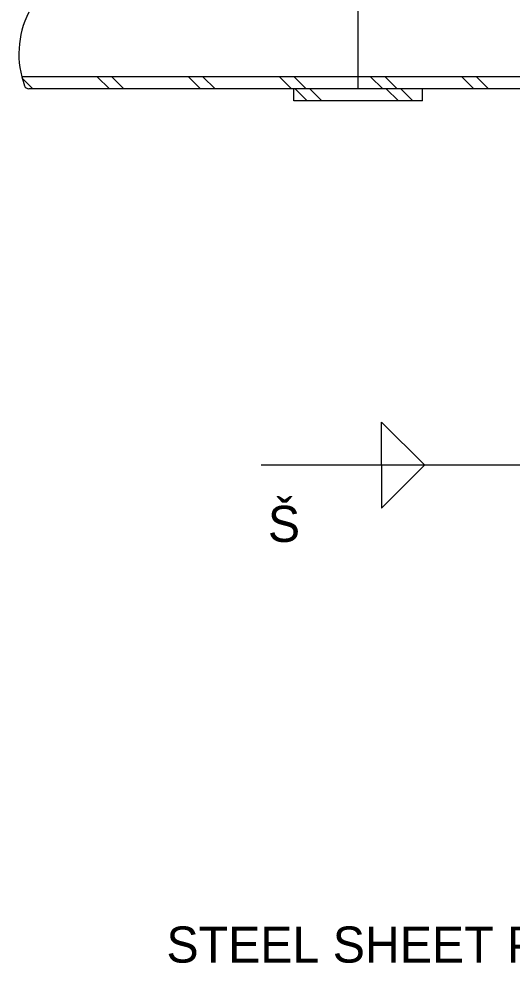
# Model space of a CAD drawing. Extents: x 22411.4 to 22495.4, y 22369.6 to 22415.
# Drawn here: x 22412.036 to 22414.588, y 22387.925 to 22392.809 of the extents above; entities that cross this region are included whole.
import ezdxf

# ---------------------------------------------------------------- set-up
doc = ezdxf.new("R2010")
doc.units = 0
for name, color, linetype in [('Level 1', 7, 'Continuous'), ('Level 10', 7, 'Continuous'), ('Level 2', 7, 'Continuous'), ('Level 4', 7, 'Continuous'), ('Level 8', 7, 'Continuous')]:
    doc.layers.add(name, color=color, linetype=linetype)

msp = doc.modelspace()

# ---------------------------------------------------------------- linework, layer by layer
at = {"layer": 'Level 1'}
for centre, radius, start, end in [((22412.516, 22392.6285), 0.4798, 153.3929, 200.1919), ((22412.0877, 22392.471), 0.0235, 200.3155, 270)]:
    msp.add_arc(centre, radius, start, end, dxfattribs=at)
at = {"layer": 'Level 10'}
for p, q in [((22413.9119, 22390.7235), (22414.1354, 22390.5)), ((22413.9119, 22390.4985), (22413.9119, 22390.7235)), ((22414.7905, 22390.5008), (22413.29, 22390.5008)), ((22413.9119, 22390.5032), (22413.9119, 22390.2782)), ((22413.9119, 22390.2782), (22414.1354, 22390.5017))]:
    msp.add_line(p, q, dxfattribs=at)
at = {"layer": 'Level 2'}
for p, q in [((22413.7912, 22392.4475), (22413.7912, 22393.2391)), ((22417.2912, 22392.51), (22412.0509, 22392.51)), ((22417.2912, 22392.4475), (22412.0877, 22392.4475)), ((22413.4578, 22392.385), (22413.4578, 22392.4475)), ((22414.1245, 22392.385), (22414.1245, 22392.4475)), ((22414.1245, 22392.385), (22413.4578, 22392.385))]:
    msp.add_line(p, q, dxfattribs=at)
at = {"layer": 'Level 8'}
for points in [[(22412.1082, 22392.4475), (22412.0509, 22392.5048)], [(22412.5042, 22392.4475), (22412.4417, 22392.51)], [(22412.5796, 22392.4475), (22412.5171, 22392.51)], [(22412.9756, 22392.4475), (22412.9131, 22392.51)], [(22413.051, 22392.4475), (22412.9885, 22392.51)], [(22413.447, 22392.4475), (22413.3845, 22392.51)], [(22413.5224, 22392.4475), (22413.4599, 22392.51)], [(22413.9184, 22392.4475), (22413.8559, 22392.51)], [(22413.9938, 22392.4475), (22413.9313, 22392.51)], [(22414.3898, 22392.4475), (22414.3273, 22392.51)], [(22414.4652, 22392.4475), (22414.4027, 22392.51)], [(22413.5277, 22392.3849), (22413.4652, 22392.4475)], [(22413.6032, 22392.3849), (22413.5407, 22392.4475)], [(22413.9991, 22392.385), (22413.9366, 22392.4475)], [(22414.0746, 22392.385), (22414.0121, 22392.4475)]]:
    msp.add_lwpolyline(points, dxfattribs=at)

# ---------------------------------------------------------------- texts
at = {"layer": 'Level 4'}
for s, height, p in [('Š', 0.1867, (22413.3244, 22390.1038)), ('STEEL SHEET PILING', 0.186667, (22412.7996, 22387.9276))]:
    msp.add_text(s, height=height, dxfattribs=at).set_placement(p)

doc.saveas('drawing.dxf')
